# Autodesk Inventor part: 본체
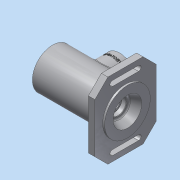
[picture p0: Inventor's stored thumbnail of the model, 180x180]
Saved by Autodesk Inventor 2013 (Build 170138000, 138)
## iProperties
Created: 2017-10
Part Number: 본체
Material: 알루미늄 6061
Document SubType Name: Modeling
Designer: dgall
Density: 2.71 g/cm^3
Mass: 738.119 g
Surface Area: 650.901 cm^2
Volume: 272.368 cm^3
Author: dgall
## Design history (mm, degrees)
sketch "스케치1"
  geometry: L1 (-57.5, 0)-(57.5, 0); L2 (-57.5, 21)-(-57.5, 31); L3 (-57.5, 31)-(44.5, 31); L4 (44.5, 35)-(57.5, 35); L5 (57.5, 35)-(57.5, 22); L6 (44.5, 35)-(44.5, 31); L7 (-57.5, 21)-(-48.5, 21); L8 (-48.5, 21)-(-48.5, 24); L9 (-48.5, 24)-(-45.5, 24); L10 (-45.5, 24)-(-45.5, 20); L11 (-45.5, 20)-(-36.5, 20); L12 (-36.5, 20)-(-36.5, 17.5); L13 (-36.5, 17.5)-(-33.25, 17.5); L14 (-33.25, 17.5)-(-33.25, 18.5); L15 (-33.25, 18.5)-(-31.5, 18.5); L16 (-31.5, 18.5)-(-31.5, 17.5); L17 (-31.5, 17.5)-(-20.5, 17.5); L18 (-20.5, 17.5)-(-20.5, 26); L19 (-20.5, 26)-(17.5, 26); L20 (17.5, 26)-(17.5, 17.5); L21 (17.5, 17.5)-(28.5, 17.5); L22 (28.5, 17.5)-(28.5, 16.5); L23 (28.5, 16.5)-(33.5, 16.5); L24 (33.5, 16.5)-(33.5, 10); L25 (33.5, 10)-(36.2, 10); L26 (36.2, 10)-(36.2, 12.5); L27 (36.2, 12.5)-(42.8, 12.5); L28 (57.5, 22)-(43.5, 16); L29 (43.5, 16)-(43.5, 12.904); L30 (42.8, 12.5)-(43.5, 12.904); 2 further points
  constraints: 60 end point, 19 parallel, 8 perpendicular, 2 horizontal alignment, 2 vertical alignment, 1 coincident, 1 horizontal, 1 midpoint
  dimensions: "d2" = 70 diameter of L4 L1; "d3" = 62 diameter of L3 L1; "d4" = 13 distance of L4.start L4.end; "d5" = 115 distance of L1.start L1.end; "d6" = 12 distance between parallel lines of L2 L10; "d7" = 3 distance of L8.end L9.end; "d8" = 42 diameter of L7 L1; "d9" = 48 diameter of L9 L1; "d10" = 40 diameter of L11 L1; "d11" = 35 diameter of L13 L1; "d12" = 21 distance between parallel lines of L2 L12; "d13" = 38 distance between parallel lines of L20 L18; "d14" = 26 distance between parallel lines of L2 L16; "d15" = 1.75 distance of L14.end L15.end; "d16" = 37 diameter of L15 L1; "d17" = 11 distance of L16.end L17.end; "d18" = 52 diameter of L19 L1; "d19" = 11 distance of L20.end L21.end; "d20" = 5 distance of L22.end L23.end; "d21" = 33 diameter of L23 L1; "d22" = 20 diameter of L25 L1; "d23" = 25 diameter of L27 L1; "d24" = 2.7 distance of L24.end L25.end; "d26" = 32 diameter of L28.end L1; "d27" = 30 deg angle of L27 L30; "d28" = 7.3 distance between parallel lines of L26 L29; "d29" = 0.7 horizontal distance of L29.end L27.end; "d30" = 44 diameter of L5.end L1
revolve "회전1" sketch "스케치1" stored, may be unused: angle "d31" = 90 deg
node "작업 평면1"
sketch "스케치2"
  geometry: L1 (-58, 47)-(58, 47); L2 (58, 47)-(58, -47); L3 (58, -47)-(-58, -47); L4 (-58, -47)-(-58, 47); L5 (-50, 20)-(-50, -20); L6 (-42, -20)-(-42, 20); L7 (42, 20)-(42, -20); L8 (50, -20)-(50, 20); C1 r 31 at (0, 0) reference; A1 r 4 centre (-46, -20) between (-50, -20) and (-42, -20); A2 r 4 centre (-46, 20) between (-42, 20) and (-50, 20); A3 r 4 centre (46, -20) between (42, -20) and (50, -20); A4 r 4 centre (46, 20) between (50, 20) and (42, 20); 3 further points
  constraints: 16 end point, 8 point on circle, 8 tangent, 4 centre point, 4 parallel, 3 horizontal alignment, 2 midpoint, 2 perpendicular, 1 equal radius, 1 horizontal, 1 vertical, 1 vertical alignment
  dimensions: "d33" = 94 distance between parallel lines of L3 L1; "d35" = 116 distance between parallel lines of L4 L2; "d36" = 40 distance of A3.centre A4.centre; "d37" = 20 vertical distance of A3.centre point (0, 0); "d38" = 92 distance of A3.centre A1.centre; "d39" = 46 horizontal distance of A1.centre point (0, 0); "d40" = 4 radius of A2
extrude "돌출1" join sketch "스케치2" distance "d41" = 10; taper "d42" = 0 deg
chamfer "모따기1" distance "d43" = 20; stored, may be unused: second distance "d44" = 2, angle "d45" = 45 deg
node "작업 평면3"
  node "작업 평면2"
sketch "스케치3"
  geometry: L1 (-51, -31)-(-51, 31) reference; C1 r 25 at (5, 0); 1 further point
  constraints: 1 centre point, 1 horizontal alignment
  dimensions: "d48" = 56 distance from line of L1 C1.centre; "d49" = 50 diameter of C1
extrude "돌출2" join sketch "스케치3" stored distance "d50" = 10; taper "d51" = 0 deg
hole "구멍1" diameter "d54" = 32; stored, may be unused: countersink angle "d58" = 90 deg, drill point angle "d60" = 118 deg; dims "d52" = 10, "d53" = 10, "d55" = 6, "d56" = 4, "d57" = 2, "d59" = 8
feature "스레드1" dims "d61" = 10, "d62" = 0
chamfer "모따기2" distance "d63" = 1; stored, may be unused: second distance "d64" = 2, angle "d65" = 45 deg
chamfer "모따기3" distance "d66" = 1; stored, may be unused: second distance "d67" = 2, angle "d68" = 45 deg
fillet "모깎기1" dims "d69" = 3
chamfer "모따기4" distance "d70" = 1; stored, may be unused: second distance "d71" = 2, angle "d72" = 45 deg
fillet "모깎기2" dims "d73" = 3
fillet "모깎기3" dims "d74" = 3
fillet "모깎기4" dims "d75" = 3
fillet "모깎기5" dims "d76" = 0.3
sketch "스케치4"
  geometry: C1 r 25 at (0, 0) reference; 3 further points
  constraints: 2 vertical alignment
  dimensions: "d77" = 41 distance of point (0, -20.5) point (0, 20.5); "d79" = 20.5 distance of C1.centre point (0, 20.5) (= 0.5 x d77)
hole "구멍2" sketch "스케치4" at (0, 20.5), (0, -20.5) diameter "d80" = 2.459; stored, may be unused: countersink angle "d84" = 90 deg, drill point angle "d86" = 118 deg; dims "d81" = 6, "d82" = 4, "d83" = 2, "d85" = 8
fillet "모깎기6" dims "d87" = 0.3
node "작업 평면5"
  node "작업 평면4"
sketch "스케치5"
  geometry: L1 (-26, -31)-(-26, 31) reference; L2 (5, 47)-(55, 47) reference; 2 further points
  constraints: 1 other
  dimensions: "d90" = 56 distance from line of point (30, 37) L1; "d91" = 10 distance from line of L2 point (30, 37)
feature "엠보싱1" sketch "스케치5" dims "d92" = 0.5, "d93" = 0
node "솔리드1"
node "작업축1"
node "작업축2"
other parameters: "d32" = -13, "d46" = 0, "d47" = 47, "d88" = 0, "d89" = 45.75
